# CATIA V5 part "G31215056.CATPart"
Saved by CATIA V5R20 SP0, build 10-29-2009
Part number: G31215056
Revision: 7
Definition: design
Nomenclature: G31215056
Source: made
Description: NOT SPECIFIED
Bounding box of the stored display mesh (mm): x -6 to 56, y -12.31 to 12.31, z -12.5 to 12.5
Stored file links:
  C:\Users\Raffaele\Desktop\3D X SITO CF\BOLEX\23-BUSH REF 312\G31215056.CATPart

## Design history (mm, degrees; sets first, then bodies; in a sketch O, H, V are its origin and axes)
Body1 "MANIFOLD_SOLID_BREP #12383" (main body)
  Solid1: solid without history
Body2 "MANIFOLD_SOLID_BREP #12526"
  Solid2: solid without history
Body3 "MANIFOLD_SOLID_BREP #12669"
  Solid3: solid without history
Body4 "MANIFOLD_SOLID_BREP #12812"
  Solid4: solid without history
Body5 "MANIFOLD_SOLID_BREP #12955"
  Solid5: solid without history
Body6 "MANIFOLD_SOLID_BREP #13100"
  Solid6: solid without history
Body7 "MANIFOLD_SOLID_BREP #13245"
  Solid7: solid without history
Body8 "MANIFOLD_SOLID_BREP #13390"
  Solid8: solid without history
Body9 "MANIFOLD_SOLID_BREP #13535"
  Solid9: solid without history
Body10 "MANIFOLD_SOLID_BREP #13680"
  Solid10: solid without history
Body11 "MANIFOLD_SOLID_BREP #13825"
  Solid11: solid without history
Body12 "MANIFOLD_SOLID_BREP #13970"
  Solid12: solid without history
Body13 "MANIFOLD_SOLID_BREP #14115"
  Solid13: solid without history
Body14 "MANIFOLD_SOLID_BREP #14260"
  Solid14: solid without history
Body15 "MANIFOLD_SOLID_BREP #14405"
  Solid15: solid without history
Body16 "MANIFOLD_SOLID_BREP #14550"
  Solid16: solid without history
Body17 "MANIFOLD_SOLID_BREP #14695"
  Solid17: solid without history
Body18 "MANIFOLD_SOLID_BREP #14840"
  Solid18: solid without history
Body19 "MANIFOLD_SOLID_BREP #14985"
  Solid19: solid without history
Body20 "MANIFOLD_SOLID_BREP #15131"
  Solid20: solid without history
Body21 "MANIFOLD_SOLID_BREP #15276"
  Solid21: solid without history
Body22 "MANIFOLD_SOLID_BREP #15421"
  Solid22: solid without history
Body23 "MANIFOLD_SOLID_BREP #15567"
  Solid23: solid without history
Body24 "MANIFOLD_SOLID_BREP #15712"
  Solid24: solid without history
Body25 "MANIFOLD_SOLID_BREP #15857"
  Solid25: solid without history
Body26 "MANIFOLD_SOLID_BREP #16002"
  Solid26: solid without history
Body27 "MANIFOLD_SOLID_BREP #16147"
  Solid27: solid without history
Body28 "MANIFOLD_SOLID_BREP #16292"
  Solid28: solid without history
Body29 "MANIFOLD_SOLID_BREP #16437"
  Solid29: solid without history
Body30 "MANIFOLD_SOLID_BREP #16582"
  Solid30: solid without history
Body31 "MANIFOLD_SOLID_BREP #16727"
  Solid31: solid without history
Body32 "MANIFOLD_SOLID_BREP #16870"
  Solid32: solid without history
Body33 "MANIFOLD_SOLID_BREP #17013"
  Solid33: solid without history
Body34 "MANIFOLD_SOLID_BREP #17158"
  Solid34: solid without history
Body35 "MANIFOLD_SOLID_BREP #17303"
  Solid35: solid without history
Body36 "MANIFOLD_SOLID_BREP #17449"
  Solid36: solid without history
Body37 "MANIFOLD_SOLID_BREP #17594"
  Solid37: solid without history
Body38 "MANIFOLD_SOLID_BREP #17739"
  Solid38: solid without history
Body39 "MANIFOLD_SOLID_BREP #17885"
  Solid39: solid without history
Body40 "MANIFOLD_SOLID_BREP #18030"
  Solid40: solid without history
Body41 "MANIFOLD_SOLID_BREP #18175"
  Solid41: solid without history
Body42 "MANIFOLD_SOLID_BREP #18320"
  Solid42: solid without history
Body43 "MANIFOLD_SOLID_BREP #18465"
  Solid43: solid without history
Body44 "MANIFOLD_SOLID_BREP #18610"
  Solid44: solid without history
Body45 "MANIFOLD_SOLID_BREP #18755"
  Solid45: solid without history
Body46 "MANIFOLD_SOLID_BREP #18900"
  Solid46: solid without history
Body47 "MANIFOLD_SOLID_BREP #19045"
  Solid47: solid without history
Body48 "MANIFOLD_SOLID_BREP #19190"
  Solid48: solid without history
Body49 "MANIFOLD_SOLID_BREP #19335"
  Solid49: solid without history
Body50 "MANIFOLD_SOLID_BREP #19481"
  Solid50: solid without history
Body51 "MANIFOLD_SOLID_BREP #19626"
  Solid51: solid without history
Body52 "MANIFOLD_SOLID_BREP #19771"
  Solid52: solid without history
Body53 "MANIFOLD_SOLID_BREP #19917"
  Solid53: solid without history
Body54 "MANIFOLD_SOLID_BREP #20062"
  Solid54: solid without history
Body55 "MANIFOLD_SOLID_BREP #20207"
  Solid55: solid without history
Body56 "MANIFOLD_SOLID_BREP #20350"
  Solid56: solid without history
Body57 "MANIFOLD_SOLID_BREP #20493"
  Solid57: solid without history
Body58 "MANIFOLD_SOLID_BREP #20638"
  Solid58: solid without history
Body59 "MANIFOLD_SOLID_BREP #20783"
  Solid59: solid without history
Body60 "MANIFOLD_SOLID_BREP #20928"
  Solid60: solid without history
Body61 "MANIFOLD_SOLID_BREP #21073"
  Solid61: solid without history
Body62 "MANIFOLD_SOLID_BREP #21218"
  Solid62: solid without history
Body63 "MANIFOLD_SOLID_BREP #21363"
  Solid63: solid without history
Body64 "MANIFOLD_SOLID_BREP #21506"
  Solid64: solid without history
Body65 "MANIFOLD_SOLID_BREP #21649"
  Solid65: solid without history
Body66 "MANIFOLD_SOLID_BREP #21794"
  Solid66: solid without history
Body67 "MANIFOLD_SOLID_BREP #21939"
  Solid67: solid without history
Body68 "MANIFOLD_SOLID_BREP #22085"
  Solid68: solid without history
Body69 "MANIFOLD_SOLID_BREP #22230"
  Solid69: solid without history
Body70 "MANIFOLD_SOLID_BREP #22375"
  Solid70: solid without history
Body71 "MANIFOLD_SOLID_BREP #22521"
  Solid71: solid without history
Body72 "MANIFOLD_SOLID_BREP #22666"
  Solid72: solid without history
Body73 "MANIFOLD_SOLID_BREP #22811"
  Solid73: solid without history
Body74 "MANIFOLD_SOLID_BREP #22956"
  Solid74: solid without history
Body75 "MANIFOLD_SOLID_BREP #23101"
  Solid75: solid without history
Body76 "MANIFOLD_SOLID_BREP #23246"
  Solid76: solid without history
Body77 "MANIFOLD_SOLID_BREP #23391"
  Solid77: solid without history
Body78 "MANIFOLD_SOLID_BREP #23536"
  Solid78: solid without history
Body79 "MANIFOLD_SOLID_BREP #23681"
  Solid79: solid without history
Body80 "MANIFOLD_SOLID_BREP #23826"
  Solid80: solid without history
Body81 "MANIFOLD_SOLID_BREP #23971"
  Solid81: solid without history
Body82 "MANIFOLD_SOLID_BREP #24117"
  Solid82: solid without history
Body83 "MANIFOLD_SOLID_BREP #24262"
  Solid83: solid without history
Body84 "MANIFOLD_SOLID_BREP #24407"
  Solid84: solid without history
Body85 "MANIFOLD_SOLID_BREP #24553"
  Solid85: solid without history
Body86 "MANIFOLD_SOLID_BREP #24698"
  Solid86: solid without history
Body87 "MANIFOLD_SOLID_BREP #24843"
  Solid87: solid without history
Body88 "MANIFOLD_SOLID_BREP #24986"
  Solid88: solid without history
Body89 "MANIFOLD_SOLID_BREP #25129"
  Solid89: solid without history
